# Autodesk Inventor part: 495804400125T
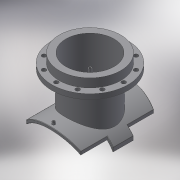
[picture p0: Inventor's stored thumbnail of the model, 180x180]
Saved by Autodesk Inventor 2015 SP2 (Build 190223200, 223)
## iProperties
Created: 2017-10
Part Number: 495804400125T
Material: Generic
Description: PLASSON FLANGED BRANCH SADDLE 250-400X150
Document SubType Name: Modeling
Designer: KIM
Density: 1 g/cm^3
Appearance: Default
Author: KIM
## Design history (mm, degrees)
derived "495904.ipt"
feature "Solid1::495904.ipt"
feature "Solid2::495904.ipt"
tag "TaggingFeature1"
body "Solid1"
other parameters: "d1" = 15, "d2" = 274.5, "d4" = 0, "d5" = 305, "d6" = 75, "d7" = 0, "d11" = 2, "d12" = 225.6, "d13" = 14, "d14" = 135, "d16" = 5 deg, "d18" = 4, "d19" = 14, "d20" = 0, "d21" = 3, "d22" = 0, "d23" = 334, "d36" = 135, "d38" = 0, "d39" = 2, "d40" = 119, "d42" = 212, "d43" = 285, "d44" = 95.2, "d46" = 169.6, "d47" = 16, "d48" = 10.4, "d49" = 83.3, "d51" = 408, "d53" = 0, "d54" = 18, "d57" = 0, "d59" = 360 deg, "d61" = 24, "d63" = 0, "d_1" = 212, "B_" = 305, "H_" = 119, "x_" = 15, "D_" = 16, "D_1" = 285, "t_" = 24, "s_" = 18
